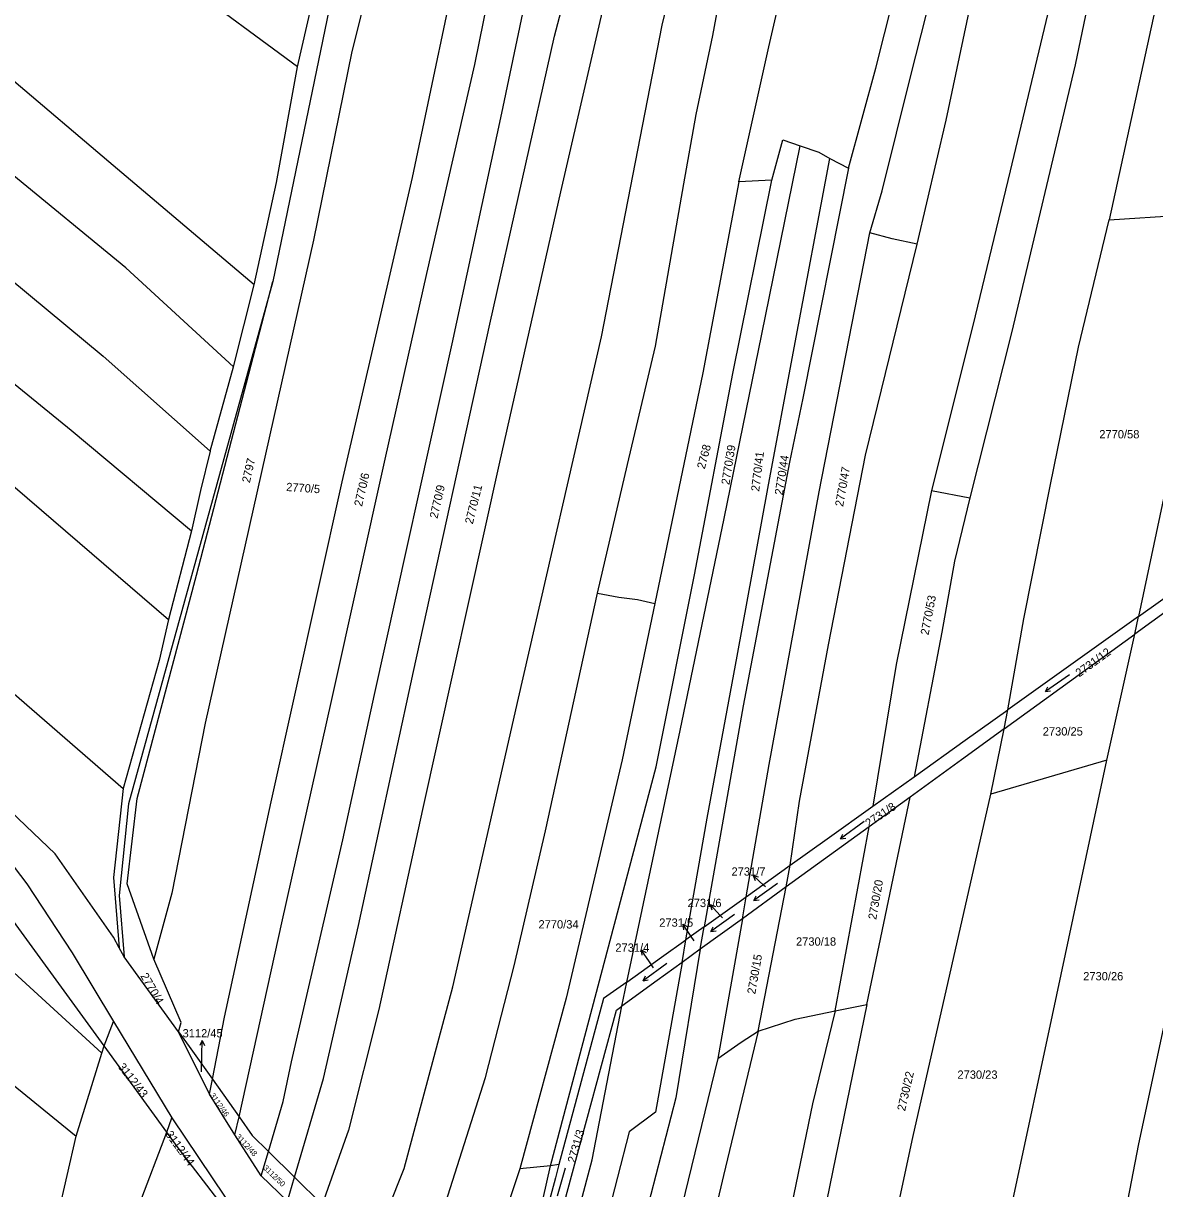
# Model space of a CAD drawing. Extents: x -776734 to -748832, y -1118122 to -976986.
# Drawn here: x -753866 to -753634.1, y -1115064.9 to -1114826.1 of the extents above; entities that cross this region are included whole.
import ezdxf

# ---------------------------------------------------------------- set-up
doc = ezdxf.new("R2010")
doc.units = 0
for name, color, linetype in [('KM_Hranice parcel', 7, 'Continuous'), ('KM_Parcelní čísla', 7, 'Continuous'), ('KM_Pop  PČ popisy', 7, 'Continuous'), ('KM_Značky kultur', 7, 'Continuous')]:
    doc.layers.add(name, color=color, linetype=linetype)

msp = doc.modelspace()

# ---------------------------------------------------------------- linework, layer by layer
at = {"layer": 'KM_Hranice parcel'}
for p, q in [((-753809.79, -1114834.95), (-753806.92, -1114822.44)), ((-753700.69, -1114853.73), (-753696.84, -1114855.73)), ((-753712.59, -1114858.19), (-753719.31, -1114858.54)), ((-753643.43, -1114866.36), (-753619.35, -1114864.71)), ((-753822.92, -1114896.46), (-753818.65, -1114879.63)), ((-753827.64, -1114913.74), (-753822.92, -1114896.46)), ((-753679.86, -1114921.84), (-753671.97, -1114923.35)), ((-753831.51, -1114930.07), (-753836.21, -1114948.23)), ((-753637.4, -1114947.63), (-753664.21, -1114966.78)), ((-753638.18, -1114951.25), (-753637.4, -1114947.63)), ((-753664.93, -1114970.65), (-753638.18, -1114951.25)), ((-753643.9, -1114977.12), (-753638.18, -1114951.25)), ((-753664.93, -1114970.65), (-753664.21, -1114966.78)), ((-753667.69, -1114984.06), (-753664.93, -1114970.65)), ((-753643.9, -1114977.12), (-753667.69, -1114984.06)), ((-753691.86, -1114986.53), (-753683.38, -1114980.47)), ((-753693.08, -1115027.16), (-753684.21, -1114984.64)), ((-753684.21, -1114984.64), (-753692.63, -1114990.74)), ((-753699.56, -1115028.45), (-753692.63, -1114990.74)), ((-753717.82, -1115005.07), (-753708.81, -1114998.64)), ((-753709.61, -1115003.06), (-753708.81, -1114998.64)), ((-753849.4, -1115035.67), (-753874.66, -1115000.95)), ((-753709.61, -1115003.06), (-753718.61, -1115009.59)), ((-753715.37, -1115032.61), (-753709.61, -1115003.06)), ((-753726.45, -1115011.23), (-753717.82, -1115005.07)), ((-753718.61, -1115009.59), (-753717.82, -1115005.07)), ((-753718.61, -1115009.59), (-753727.25, -1115015.85)), ((-753718.61, -1115009.59), (-753723.63, -1115038.25)), ((-753726.45, -1115011.23), (-753730.18, -1115013.9)), ((-753727.25, -1115015.85), (-753726.45, -1115011.23)), ((-753845.32, -1115017.37), (-753846.3, -1115015.57)), ((-753730.97, -1115018.56), (-753730.18, -1115013.9)), ((-753834.13, -1115032.77), (-753845.32, -1115017.37)), ((-753727.25, -1115015.85), (-753730.97, -1115018.56)), ((-753743.32, -1115027.52), (-753742.31, -1115022.56)), ((-753699.56, -1115028.45), (-753693.08, -1115027.16)), ((-753849.4, -1115035.67), (-753847.51, -1115030.62)), ((-753847.51, -1115030.62), (-753835.51, -1115050.38)), ((-753827.82, -1115045.56), (-753834.13, -1115032.77)), ((-753855.1, -1115054.13), (-753849.85, -1115037.13)), ((-753849.85, -1115037.13), (-753849.4, -1115035.67)), ((-753836.55, -1115053.32), (-753849.4, -1115035.67)), ((-753827.82, -1115045.56), (-753827.22, -1115042.47)), ((-753827.22, -1115042.47), (-753821.74, -1115050.21)), ((-753822.65, -1115053.88), (-753827.82, -1115045.56)), ((-753836.55, -1115053.32), (-753835.51, -1115050.38)), ((-753835.51, -1115050.38), (-753824.6, -1115066.64)), ((-753822.65, -1115053.88), (-753821.74, -1115050.21)), ((-753817.24, -1115062.32), (-753822.65, -1115053.88)), ((-753859.25, -1115072.07), (-753855.1, -1115054.13)), ((-753817.24, -1115062.32), (-753815.75, -1115057.27)), ((-753815.75, -1115057.27), (-753810.37, -1115062.57)), ((-753764.22, -1115060.84), (-753775.17, -1115093.59)), ((-753767.01, -1115100.3), (-753757.9, -1115060.21)), ((-753757.9, -1115060.21), (-753764.22, -1115060.84)), ((-753756.2, -1115059.98), (-753757.9, -1115060.21)), ((-753811.82, -1115067.51), (-753817.24, -1115062.32)), ((-753811.82, -1115067.51), (-753810.37, -1115062.57)), ((-753810.37, -1115062.57), (-753804.69, -1115068.16))]:
    msp.add_line(p, q, dxfattribs=at)
for points in [[(-753794.59, -1115077.61), (-753787.93, -1115060.8), (-753777.91, -1115023.56), (-753764.5, -1114964.39), (-753747.45, -1114890.29), (-753735.04, -1114826.44), (-753725.78, -1114788.24), (-753719.01, -1114758.28), (-753706.47, -1114700.23), (-753694.32, -1114647.7), (-753687.72, -1114622.89), (-753664.72, -1114512.91)], [(-753748.31, -1114942.85), (-753742.18, -1114916.5), (-753736.38, -1114892.22), (-753730.62, -1114858.93), (-753728.07, -1114844.73), (-753724.64, -1114828.54), (-753723.28, -1114821.11), (-753709.62, -1114765.41), (-753699.36, -1114718.72), (-753689.49, -1114676.33), (-753681.62, -1114644.48), (-753672.27, -1114601.8), (-753665.84, -1114570.01), (-753657.14, -1114527.54)], [(-753719.31, -1114858.54), (-753713.16, -1114830.85), (-753703.28, -1114787.85), (-753686.64, -1114715.99), (-753670.27, -1114646.05), (-753666.14, -1114626.53), (-753658.11, -1114585.95), (-753650.23, -1114541.59)], [(-753696.84, -1114855.73), (-753691.24, -1114835.28), (-753680.55, -1114792.69), (-753674.32, -1114768), (-753656.4, -1114685.57), (-753648.33, -1114645.93), (-753640.26, -1114607.21), (-753633.95, -1114573.16)], [(-753692.5, -1114869), (-753689.97, -1114860.37), (-753684.09, -1114836.72), (-753674.61, -1114799.31), (-753666.41, -1114766.32), (-753660.14, -1114736.05), (-753657.6, -1114725.49), (-753649.09, -1114683.97), (-753643.82, -1114656.31), (-753638.66, -1114631.83), (-753631.88, -1114599.38), (-753628.52, -1114582.03)], [(-753682.77, -1114871.3), (-753676.87, -1114845.91), (-753670.36, -1114815.19), (-753661.87, -1114778.82), (-753643.37, -1114691.82), (-753635.78, -1114652.49), (-753628.1, -1114616.86), (-753622.99, -1114590.06)], [(-753610.25, -1114606.01), (-753617.12, -1114637.26), (-753624.49, -1114671.37), (-753632.34, -1114710.29), (-753639.7, -1114745.63), (-753646.59, -1114780.5), (-753654.58, -1114817.91), (-753663.71, -1114856.29), (-753671.41, -1114887.98), (-753679.86, -1114921.84)], [(-753604.79, -1114614.61), (-753613.99, -1114658.59), (-753629.87, -1114737.18), (-753640.64, -1114787.58), (-753650.44, -1114834.53), (-753663.46, -1114889.5), (-753671.97, -1114923.35)], [(-753592.96, -1114636.98), (-753601.26, -1114669.82), (-753605.55, -1114692.31), (-753616.04, -1114739.83), (-753628.68, -1114798.6), (-753643.43, -1114866.36)], [(-754041.97, -1114743.62), (-754020.4, -1114757.62), (-753979.29, -1114788.68), (-753943.78, -1114817.9), (-753872.64, -1114875.24), (-753849.61, -1114894.28), (-753827.64, -1114913.74)], [(-753822.92, -1114896.46), (-753844.96, -1114876.16), (-753869.04, -1114856.34), (-753925.76, -1114809.8), (-753967.86, -1114775.67), (-753977.3, -1114769.5), (-754007.59, -1114747.71)], [(-753818.65, -1114879.63), (-753848.46, -1114854.46), (-753887.44, -1114821.39), (-753916.04, -1114797.97), (-753953.24, -1114770.51), (-753981.41, -1114751.55)], [(-754042.84, -1114760.47), (-753990.38, -1114799.67), (-753951.29, -1114831.07), (-753902.83, -1114871.49), (-753856.19, -1114909.47), (-753831.51, -1114930.07)], [(-753809.79, -1114834.95), (-753856.88, -1114800.2), (-753890.97, -1114776.38), (-753909.62, -1114763.9)], [(-754044.32, -1114776.03), (-754030.98, -1114786.91), (-753996.74, -1114815.81), (-753928.78, -1114871.72), (-753884.71, -1114908.95), (-753867.63, -1114921.23), (-753836.21, -1114948.23)], [(-753791.42, -1114802.85), (-753798.62, -1114831.84), (-753806.47, -1114870.47), (-753828.68, -1114969.47), (-753835.5, -1115004.32), (-753839.23, -1115017.91)], [(-753798.57, -1114801.23), (-753799.91, -1114806.81), (-753814.84, -1114878.99)], [(-753827.22, -1115042.47), (-753824.75, -1115029.79), (-753815.18, -1114985.65), (-753800.65, -1114920.02), (-753786.23, -1114857.67), (-753775.22, -1114805.4)], [(-753821.74, -1115050.21), (-753812.98, -1115010.4), (-753802.75, -1114964.66), (-753791.79, -1114915.39), (-753783.28, -1114877.36), (-753773.41, -1114834.52), (-753767.91, -1114807.15)], [(-753815.75, -1115057.27), (-753812.74, -1115047.08), (-753811.02, -1115038.9), (-753800.47, -1114993.4), (-753793.97, -1114963.65), (-753778.1, -1114891.75), (-753767.92, -1114844.45), (-753760.42, -1114808.97)], [(-754049.2, -1114812.72), (-754036.01, -1114822.08), (-754012.74, -1114841.09), (-753983.63, -1114866.72), (-753971.24, -1114876.69), (-753931.67, -1114908.95), (-753885.6, -1114948.11), (-753845.51, -1114982.89)], [(-753810.37, -1115062.57), (-753804.42, -1115042.36), (-753797.25, -1115010.97), (-753786.03, -1114958.91), (-753770.33, -1114887.7), (-753757.09, -1114828.71), (-753752.47, -1114811.02)], [(-753744.88, -1114812.91), (-753755.85, -1114860.59), (-753768.37, -1114915.99), (-753784.17, -1114987.23), (-753793.11, -1115028.22), (-753799.33, -1115052.95), (-753804.69, -1115068.16)], [(-753846.3, -1115015.57), (-753847.5, -1115013.36), (-753859.43, -1114996.29), (-753882.16, -1114974.61), (-753901.4, -1114957.76), (-753966.16, -1114903.86), (-754029.82, -1114852.02), (-754051.82, -1114836.8), (-754055.78, -1114834.64)], [(-753818.65, -1114879.63), (-753814.09, -1114858.7), (-753809.79, -1114834.95)], [(-754057.77, -1114843.56), (-754044.74, -1114850.31), (-754021.59, -1114869.03), (-753971.49, -1114910.21), (-753933.49, -1114941.28), (-753890.38, -1114976.24), (-753873.1, -1114992.21), (-753865.25, -1115002.44), (-753855.92, -1115016.59), (-753847.51, -1115030.62)], [(-753712.59, -1114858.19), (-753710.3, -1114849.92), (-753706.78, -1114851.17)], [(-753742.31, -1115022.56), (-753731.36, -1114971.01), (-753722.37, -1114927.57), (-753714.62, -1114889.79), (-753706.78, -1114851.17)], [(-753706.78, -1114851.17), (-753702.97, -1114852.46), (-753700.69, -1114853.73)], [(-753849.85, -1115037.13), (-753876.18, -1115013.07), (-753915.69, -1114976.48), (-753931.84, -1114963.31), (-753989.49, -1114917.04), (-754021.16, -1114890.28), (-754060.35, -1114854.28)], [(-753730.18, -1115013.9), (-753725.82, -1114989.01), (-753719.68, -1114955.74), (-753713.42, -1114921.39), (-753707.99, -1114892.59), (-753700.69, -1114853.73)], [(-753696.84, -1114855.73), (-753706.19, -1114902.92), (-753708.97, -1114916.04), (-753718.45, -1114965.98), (-753726.45, -1115011.23)], [(-753757.9, -1115060.21), (-753736.3, -1114978.48), (-753728.43, -1114939.11), (-753720.55, -1114897.8), (-753712.59, -1114858.19)], [(-753719.31, -1114858.54), (-753726.69, -1114897.7), (-753736.52, -1114944.98)], [(-753619.35, -1114864.71), (-753629.9, -1114912.16), (-753637.4, -1114947.63)], [(-753664.21, -1114966.78), (-753660.94, -1114948.11), (-753655.49, -1114920.56), (-753649.69, -1114892.45), (-753643.43, -1114866.36)], [(-754063.96, -1114868.22), (-754037.37, -1114894.75), (-754013.74, -1114915.14), (-753990.33, -1114936.58), (-753968.41, -1114954.4), (-753932.97, -1114984.35), (-753902.06, -1115012.16), (-753869.16, -1115042.73), (-753855.1, -1115054.13)], [(-753717.82, -1115005.07), (-753713.13, -1114977.96), (-753702.87, -1114922.12), (-753692.5, -1114869)], [(-753682.77, -1114871.3), (-753687.94, -1114870.26), (-753692.5, -1114869)], [(-753708.81, -1114998.64), (-753706.89, -1114985.49), (-753700.93, -1114953.44), (-753693.37, -1114914.59), (-753682.77, -1114871.3)], [(-753814.84, -1114878.99), (-753844.43, -1114986.07), (-753846.34, -1115004.81), (-753845.32, -1115017.37)], [(-753839.23, -1115017.91), (-753844.69, -1115002.42), (-753842.65, -1114984.97), (-753830.5, -1114939.15), (-753814.84, -1114878.99)], [(-753827.64, -1114913.74), (-753829.68, -1114921.78), (-753831.51, -1114930.07)], [(-753679.86, -1114921.84), (-753687.06, -1114957.47), (-753691.86, -1114986.53)], [(-753671.97, -1114923.35), (-753675.11, -1114936.31), (-753677.74, -1114950.87), (-753683.38, -1114980.47)], [(-753637.4, -1114947.63), (-753615.39, -1114931.91), (-753608.87, -1114929.33)], [(-753609.34, -1114931.95), (-753614.57, -1114934.12), (-753638.18, -1114951.25)], [(-753785.83, -1115084.82), (-753779.91, -1115069.41), (-753771.27, -1115042.16), (-753765.37, -1115019.27), (-753758.96, -1114991.55), (-753748.31, -1114942.85)], [(-753748.31, -1114942.85), (-753743.89, -1114943.66), (-753740.11, -1114944.16), (-753736.52, -1114944.98)], [(-753736.52, -1114944.98), (-753743.25, -1114976.99), (-753754.73, -1115025.85), (-753764.22, -1115060.84)], [(-753836.21, -1114948.23), (-753838.1, -1114956.69), (-753845.51, -1114982.89)], [(-753683.38, -1114980.47), (-753672.94, -1114973.02), (-753664.21, -1114966.78)], [(-753664.93, -1114970.65), (-753673.7, -1114977.02), (-753684.21, -1114984.64)], [(-753670.83, -1115102.32), (-753662.8, -1115065.45), (-753655.03, -1115029.36), (-753643.9, -1114977.12)], [(-753619.54, -1114977.59), (-753625.43, -1114999.63), (-753637.42, -1115055.73), (-753643.69, -1115088.29)], [(-753845.51, -1114982.89), (-753847.49, -1115001.12), (-753846.3, -1115015.57)], [(-753696.62, -1115114.96), (-753683.7, -1115054.43), (-753667.69, -1114984.06)], [(-753708.81, -1114998.64), (-753701.25, -1114993.24), (-753691.86, -1114986.53)], [(-753692.63, -1114990.74), (-753702.01, -1114997.55), (-753709.61, -1115003.06)], [(-753742.31, -1115022.56), (-753735.18, -1115017.47), (-753730.18, -1115013.9)], [(-753834.13, -1115032.77), (-753833.6, -1115030.89), (-753839.23, -1115017.91)], [(-753727.25, -1115015.85), (-753732.26, -1115046.29), (-753742.51, -1115085.92), (-753748.89, -1115112.2)], [(-753730.97, -1115018.56), (-753736.42, -1115049.25), (-753741.79, -1115053.28), (-753748.97, -1115081.15), (-753755.69, -1115107.74)], [(-753730.97, -1115018.56), (-753736.09, -1115022.27), (-753743.32, -1115027.52)], [(-753742.31, -1115022.56), (-753747.09, -1115025.97), (-753756.2, -1115059.98)], [(-753764.36, -1115102.04), (-753753.61, -1115062.35), (-753744.4, -1115028.3), (-753743.32, -1115027.52)], [(-753760.72, -1115104.43), (-753754.71, -1115079.05), (-753749.42, -1115058.99), (-753743.32, -1115027.52)], [(-753693.08, -1115027.16), (-753702.48, -1115072.87), (-753707.46, -1115096.26), (-753714.63, -1115123.75)], [(-753699.56, -1115028.45), (-753704.22, -1115047.53), (-753713.98, -1115094.82), (-753720.64, -1115117.31), (-753723.41, -1115128.04)], [(-753715.37, -1115032.61), (-753707.8, -1115030.19), (-753699.56, -1115028.45)], [(-753834.13, -1115032.77), (-753831.96, -1115035.76), (-753827.22, -1115042.47)], [(-753715.37, -1115032.61), (-753722.47, -1115062.21), (-753736.31, -1115120.99)], [(-753723.63, -1115038.25), (-753718.84, -1115034.92), (-753715.37, -1115032.61)], [(-753723.63, -1115038.25), (-753736.39, -1115090.66), (-753742.3, -1115116.53)], [(-753821.74, -1115050.21), (-753819.04, -1115054.03), (-753815.75, -1115057.27)], [(-753889.22, -1115281.32), (-753884.22, -1115266.45), (-753874.89, -1115225.11), (-753861.01, -1115153.01), (-753848.53, -1115088.3), (-753842.2, -1115068.25), (-753836.55, -1115053.32)], [(-753825.23, -1115068.3), (-753834.4, -1115056.28), (-753836.55, -1115053.32)], [(-753756.2, -1115059.98), (-753756.93, -1115062.71), (-753767.01, -1115100.3)]]:
    msp.add_lwpolyline(points, dxfattribs=at)
at = {"layer": 'KM_Pop  PČ popisy'}
for p, q in [((-753714.19, -1115002.76), (-753716.385, -1115000.713)), ((-753716.385, -1115000.713), (-753715.311, -1115001.03)), ((-753716.385, -1115000.713), (-753715.994, -1115001.763)), ((-753713.85, -1115003.08), (-753714.19, -1115002.76)), ((-753723.15, -1115008.9), (-753725.197, -1115006.705)), ((-753725.197, -1115006.705), (-753724.147, -1115007.096)), ((-753725.197, -1115006.705), (-753724.88, -1115007.779)), ((-753729.11, -1115013.22), (-753730.788, -1115010.732)), ((-753730.788, -1115010.732), (-753729.813, -1115011.282)), ((-753730.788, -1115010.732), (-753730.643, -1115011.842)), ((-753722.69, -1115009.39), (-753723.15, -1115008.9)), ((-753728.51, -1115014.11), (-753729.11, -1115013.22)), ((-753737.65, -1115018.42), (-753739.328, -1115015.932)), ((-753739.328, -1115015.932), (-753738.353, -1115016.482)), ((-753739.328, -1115015.932), (-753739.183, -1115017.042)), ((-753736.84, -1115019.65), (-753737.65, -1115018.42)), ((-753829.298, -1115034.579), (-753829.816, -1115035.572)), ((-753829.35, -1115037.58), (-753829.298, -1115034.579)), ((-753829.298, -1115034.579), (-753828.814, -1115035.59)), ((-753829.42, -1115040.97), (-753829.35, -1115037.58))]:
    msp.add_line(p, q, dxfattribs=at)
at = {"layer": 'KM_Značky kultur'}
for p, q in [((-753651.602, -1114959.602), (-753656.516, -1114963.044)), ((-753656.516, -1114963.044), (-753656.004, -1114962.072)), ((-753656.516, -1114963.044), (-753655.428, -1114962.894)), ((-753693.673, -1114989.628), (-753698.465, -1114993.239)), ((-753698.465, -1114993.239), (-753697.986, -1114992.25)), ((-753698.465, -1114993.239), (-753697.383, -1114993.051)), ((-753711.392, -1115002.36), (-753716.246, -1115005.886)), ((-753716.246, -1115005.886), (-753715.75, -1115004.906)), ((-753716.246, -1115005.886), (-753715.161, -1115005.718)), ((-753720.232, -1115008.69), (-753725.086, -1115012.216)), ((-753725.086, -1115012.216), (-753724.59, -1115011.236)), ((-753725.086, -1115012.216), (-753724.001, -1115012.048)), ((-753734.112, -1115018.76), (-753738.966, -1115022.286)), ((-753738.966, -1115022.286), (-753738.47, -1115021.306)), ((-753738.966, -1115022.286), (-753737.881, -1115022.118)), ((-753754.896, -1115060.69), (-753756.55, -1115066.458))]:
    msp.add_line(p, q, dxfattribs=at)

# ---------------------------------------------------------------- texts
at = {"layer": 'KM_Parcelní čísla'}
for s, p in [('2770/58', (-753645.46, -1114911.13)), ('2730/25', (-753657.05, -1114972.04)), ('2731/7', (-753720.835, -1115000.76)), ('2731/6', (-753729.835, -1115007.2)), ('2770/34', (-753760.39, -1115011.59)), ('2731/5', (-753735.645, -1115011.23)), ('2730/18', (-753707.61, -1115015.11)), ('2731/4', (-753744.635, -1115016.36)), ('2730/26', (-753648.76, -1115022.22)), ('3112/45', (-753833.33, -1115033.91)), ('2730/23', (-753674.53, -1115042.39))]:
    msp.add_text(s, height=1.7, dxfattribs=at).set_placement(p)
for s, height, rotation, p in [('2768', 1.7, 75, (-753726.318, -1114917.519)), ('2770/39', 1.7, 81, (-753721.27, -1114920.732)), ('2797', 1.7, 77, (-753819.551, -1114920.361)), ('2770/41', 1.7, 83, (-753715.166, -1114922.083)), ('2770/44', 1.7, 81, (-753710.34, -1114922.842)), ('2770/47', 1.7, 80, (-753697.972, -1114925.217)), ('2770/5', 1.7, 356, (-753812.139, -1114921.907)), ('2770/6', 1.7, 77, (-753796.561, -1114925.201)), ('2770/9', 1.7, 77, (-753781.101, -1114927.671)), ('2770/11', 1.7, 76, (-753773.865, -1114928.815)), ('2770/53', 1.7, 79, (-753680.465, -1114951.542)), ('2731/12', 1.7, 36, (-753649.57, -1114960.137)), ('2731/8', 1.7, 34, (-753692.717, -1114990.912)), ('2730/20', 1.7, 80, (-753691.182, -1115009.867)), ('2730/15', 1.7, 80, (-753715.972, -1115025.147)), ('2770/4', 1.7, 300, (-753842.026, -1115021.295)), ('3112/43', 1.7, 308, (-753846.669, -1115039.973)), ('2730/22', 1.7, 77, (-753685.271, -1115049.111)), ('3112/46', 1.14, 305, (-753827.774, -1115045.791)), ('3112/44', 1.7, 306, (-753836.927, -1115053.799)), ('3112/48', 1.14, 313, (-753822.499, -1115054.364)), ('2731/3', 1.7, 74, (-753752.852, -1115059.794)), ('3112/50', 1.14, 316, (-753816.893, -1115060.798))]:
    msp.add_text(s, height=height, rotation=rotation, dxfattribs=at).set_placement(p)

doc.saveas('drawing.dxf')
